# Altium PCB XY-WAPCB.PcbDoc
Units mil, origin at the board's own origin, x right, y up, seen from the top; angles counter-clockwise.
Board outline 6000 x 4000 mil, 2 copper layers (Top Layer, Bottom Layer); 0 components, 0 nets, 8 pads, 0 vias.
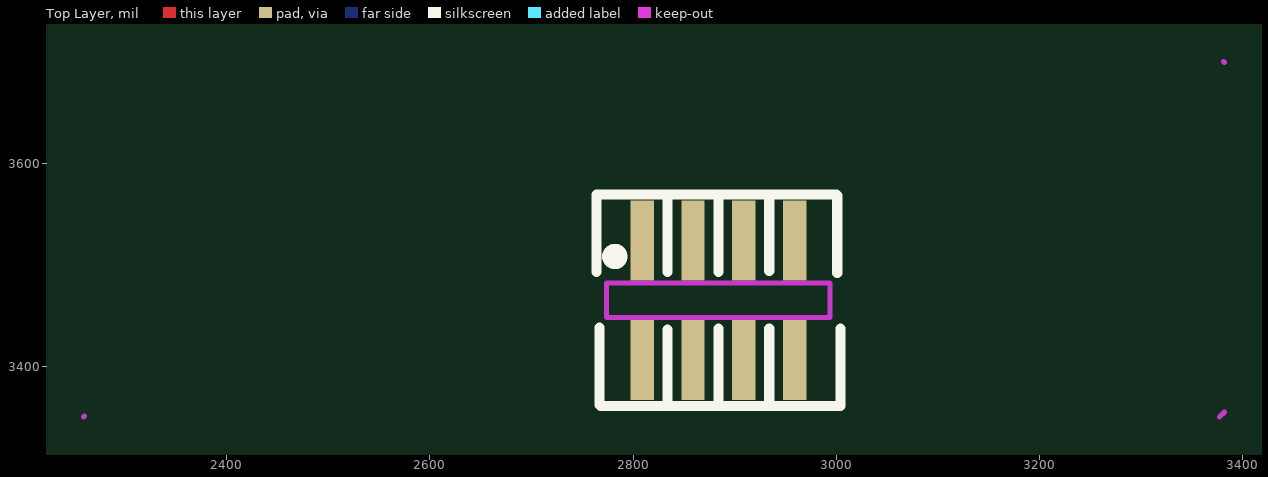
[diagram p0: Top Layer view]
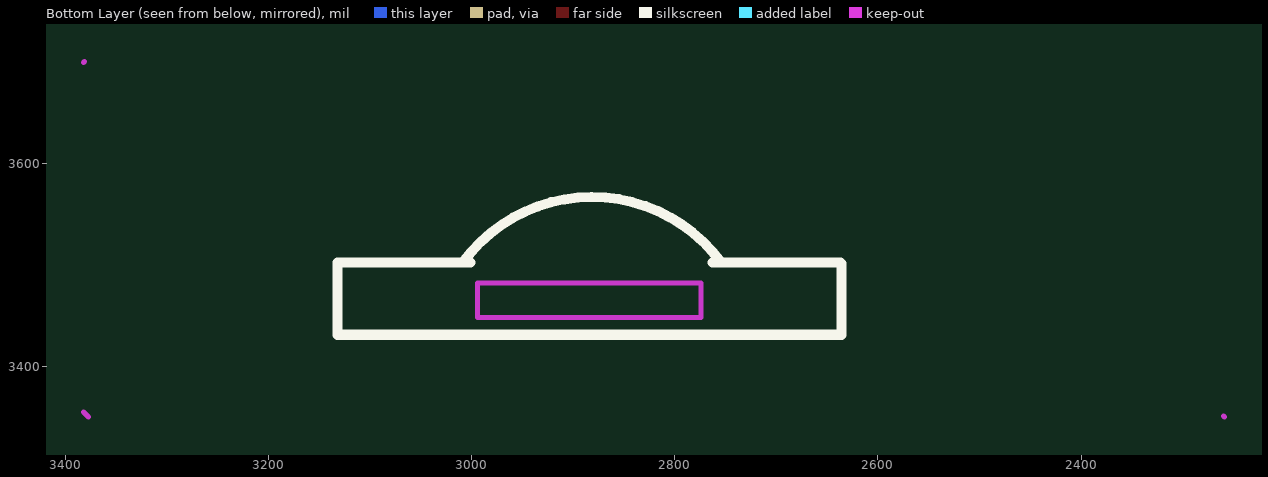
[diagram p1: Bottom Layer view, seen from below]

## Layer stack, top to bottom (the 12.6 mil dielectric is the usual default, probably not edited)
Top Layer: signal copper 1.4
Dielectric: dielectric 12.6, FR-4, Dk 4.8
Bottom Layer: signal copper 1.4

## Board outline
1000,1000 7000,1000 7000,5000 1000,5000

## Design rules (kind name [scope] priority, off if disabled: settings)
Clearance [All] p1: gap=10
PolygonConnect [All] p1: connectstyle=Relief reliefconductorwidth=10 reliefentries=4 polygonreliefangle="90 Angle"
RoutingVias [All] p1: holewidth=28 width=50 viastyle="Through Hole" minholewidth=28 minwidth=50 maxholewidth=28 maxwidth=50
SilkscreenOverComponentPads [All] p1: minsilkscreentomaskgap=10
SolderMaskExpansion [All] p1: expansion=4
Width [All] p1: maxlimit=10 minlimit=10 preferedwidth=10
27 further rules are at their usual default settings.

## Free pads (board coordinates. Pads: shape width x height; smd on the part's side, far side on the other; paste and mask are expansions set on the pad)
  rect 23x78.74 smd: 1(2809,3524) 2(2859,3524) 3(2909,3524) 4(2959,3524) 5(2959,3406) 6(2909,3406) 7(2859,3406) 8(2809,3406)

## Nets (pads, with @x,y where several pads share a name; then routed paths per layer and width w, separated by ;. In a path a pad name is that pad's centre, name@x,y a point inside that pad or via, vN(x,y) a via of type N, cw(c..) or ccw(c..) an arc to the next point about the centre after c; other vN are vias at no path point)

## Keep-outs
Keep-Out Layer:
  lines w5: 2259,3350 2260,3351 ; 3377,3350 3382,3355 ; 3381,3700 3382,3699 ; 2774,3448 2774,3482 2994,3482 2994,3448 2774,3448

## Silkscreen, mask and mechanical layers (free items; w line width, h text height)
Top Overlay:
  circle w15: c2782,3508 r5
  lines w10: 2764,3493 2764,3569 ; 2765,3569 3000,3569 ; 2767,3362 2767,3438 ; 2768,3361 3003,3361 ; 2834,3361 2834,3436 ; 2834,3493 2834,3569 ; 2884,3361 2884,3437 ; 2884,3493 2884,3569 ; 2934,3361 2934,3437 ; 2934,3494 2934,3569 ; 3001,3492 3001,3568 ; 3004,3361 3004,3437
Bottom Overlay:
  lines w9.84: 2754.54,3502.34 cw(c2881.5,3409.17) 3008.81,3501.86
  lines w10: 2635.97,3501 2635.97,3431 3132.03,3431 ; 2636.97,3502 2763,3502 ; 3001,3502 3132,3502 3132,3432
